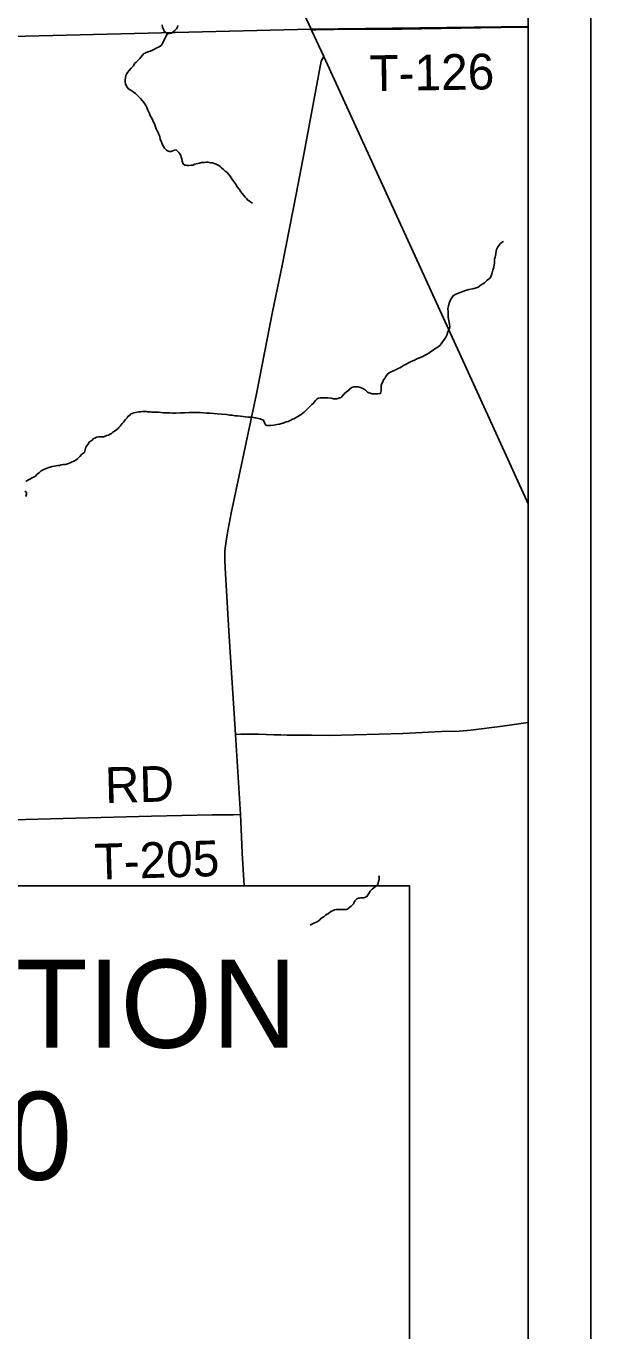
# Model space of a CAD drawing. Extents: x 0 to 34, y 0 to 22.
# Drawn here: x 8.364 to 9.262, y 17.696 to 19.769 of the extents above; entities that cross this region are included whole.
import ezdxf

# ---------------------------------------------------------------- set-up
doc = ezdxf.new("R2010")
doc.units = 0
for name, color, linetype in [('GM_X_County', 7, 'Continuous'), ('GM_X_County_Road', 7, 'Continuous'), ('GM_X_Minor_Lake', 7, 'Continuous'), ('GM_X_Minor_River', 7, 'Continuous'), ('GM_X_State_Route', 7, 'Continuous'), ('GM_X_Township', 7, 'Continuous'), ('GM_X_Township_Road', 7, 'Continuous'), ('GM_X_Township_Road_Text', 7, 'Continuous'), ('SH_Border', 7, 'Continuous'), ('SH_Data', 7, 'Continuous'), ('SH_Text', 7, 'Continuous')]:
    doc.layers.add(name, color=color, linetype=linetype)

msp = doc.modelspace()

# ---------------------------------------------------------------- linework, layer by layer
at = {"layer": 'GM_X_County'}
msp.add_lwpolyline([(9.1622, 14.342), (9.1622, 21.1385), (2.3622, 21.1385), (2.3622, 14.3385), (9.0003, 14.3385)], dxfattribs=at)
at = {"layer": 'GM_X_County_Road'}
msp.add_lwpolyline([(8.7102, 18.4031), (8.7074, 18.4551), (8.7054, 18.4937), (8.7044, 18.5161), (8.6966, 18.6436), (8.6868, 18.7992), (8.6805, 18.8991), (8.6795, 18.9191), (8.6795, 18.9355), (8.6817, 18.9511), (8.6849, 18.9697), (8.69, 18.9951), (8.7298, 19.1848), (8.7557, 19.3152), (8.7706, 19.389), (8.7936, 19.505), (8.8058, 19.5687), (8.8326, 19.7135), (8.8373, 19.7211)], dxfattribs=at)
at = {"layer": 'GM_X_Minor_Lake'}
msp.add_lwpolyline([(8.5798, 19.7717), (8.5806, 19.7679), (8.5818, 19.7656), (8.5833, 19.7614), (8.5864, 19.7588), (8.5883, 19.7577), (8.5902, 19.7577), (8.5925, 19.7577), (8.5947, 19.7581), (8.5977, 19.7604), (8.6004, 19.7627), (8.603, 19.7654), (8.6045, 19.7677), (8.6049, 19.7707)], dxfattribs=at)
at = {"layer": 'GM_X_Minor_River'}
for points in [[(8.5883, 19.7577), (8.5789, 19.739), (8.5755, 19.7367), (8.5714, 19.7347), (8.568, 19.7328), (8.5646, 19.7313), (8.5608, 19.7297), (8.5578, 19.7286), (8.5547, 19.7274), (8.5528, 19.7266), (8.551, 19.7259), (8.5491, 19.7239), (8.5461, 19.7201), (8.5446, 19.7182), (8.5415, 19.7148), (8.5389, 19.7121), (8.5363, 19.7098), (8.5344, 19.7064), (8.5306, 19.7025), (8.5276, 19.6987), (8.525, 19.6957), (8.5235, 19.693), (8.5224, 19.6907), (8.5213, 19.6835), (8.5213, 19.6804), (8.5217, 19.6778), (8.5229, 19.6751), (8.5244, 19.6725), (8.5259, 19.6702), (8.5282, 19.6687), (8.5301, 19.6676), (8.5324, 19.6661), (8.5355, 19.6638), (8.5374, 19.6623), (8.5397, 19.6604), (8.5424, 19.6574), (8.5454, 19.6544), (8.5481, 19.651), (8.5508, 19.6483), (8.5527, 19.6457), (8.5542, 19.6431), (8.5554, 19.64), (8.5569, 19.637), (8.5585, 19.6336), (8.56, 19.6306), (8.5612, 19.6275), (8.5627, 19.6245), (8.5647, 19.6211), (8.5658, 19.6181), (8.5674, 19.615), (8.5685, 19.6124), (8.5693, 19.6093), (8.5705, 19.6063), (8.572, 19.6029), (8.5735, 19.6003), (8.5747, 19.5972), (8.5762, 19.5938), (8.577, 19.59), (8.5782, 19.5862), (8.5794, 19.584), (8.5805, 19.5809), (8.5821, 19.5779), (8.584, 19.5753), (8.5867, 19.5722), (8.5886, 19.5711), (8.5916, 19.57), (8.5943, 19.57), (8.5999, 19.5723), (8.6022, 19.5727), (8.6049, 19.5701), (8.6072, 19.5678), (8.6087, 19.5656), (8.6099, 19.5637), (8.6103, 19.561), (8.6111, 19.5584), (8.6118, 19.5549), (8.6126, 19.5531), (8.6134, 19.5508), (8.6161, 19.5485), (8.618, 19.5482), (8.6202, 19.5478), (8.6229, 19.5478), (8.6259, 19.5482), (8.6286, 19.5486), (8.632, 19.5498), (8.6343, 19.5506), (8.6365, 19.5509), (8.6392, 19.5517), (8.6426, 19.5525), (8.6468, 19.5529), (8.6506, 19.553), (8.6532, 19.553), (8.6551, 19.5526), (8.6574, 19.5522), (8.6601, 19.5519), (8.6627, 19.5511)], [(8.6627, 19.5511), (8.6658, 19.55), (8.6681, 19.5489), (8.6703, 19.5478), (8.6726, 19.5459), (8.6745, 19.544), (8.6776, 19.5418), (8.6803, 19.5391), (8.6826, 19.5372), (8.686, 19.5335), (8.6879, 19.5308), (8.691, 19.5267), (8.6937, 19.5229), (8.6964, 19.5187), (8.6994, 19.5142), (8.7025, 19.5104), (8.7052, 19.5062), (8.7121, 19.4975), (8.714, 19.4957), (8.7163, 19.493), (8.7182, 19.4919), (8.7209, 19.4896), (8.7228, 19.4885), (8.7239, 19.4878)], [(8.9111, 19.1859), (8.9133, 19.1852), (8.9228, 19.1849), (8.9255, 19.1853), (8.9274, 19.1857), (8.9285, 19.1898), (8.9285, 19.194), (8.9284, 19.1963), (8.9284, 19.1982), (8.9295, 19.2016), (8.9307, 19.2043), (8.9322, 19.207), (8.9344, 19.2104), (8.9359, 19.2127), (8.9378, 19.2157), (8.9412, 19.2184), (8.9453, 19.2207), (8.9491, 19.2223), (8.9514, 19.2231), (8.9533, 19.2242), (8.9555, 19.2254), (8.9578, 19.2265), (8.9605, 19.2281), (8.9639, 19.23), (8.968, 19.2323), (8.9718, 19.2342), (8.976, 19.2362), (8.9801, 19.2381), (8.9847, 19.2404), (8.9892, 19.2423), (8.9937, 19.2439), (8.9971, 19.2458), (9.0005, 19.2477), (9.0039, 19.2497), (9.0066, 19.2516), (9.0096, 19.2531), (9.0153, 19.2574), (9.0183, 19.2589), (9.0221, 19.2623), (9.0236, 19.2643), (9.0284, 19.2715), (9.0307, 19.2742), (9.0329, 19.2784), (9.0344, 19.2833), (9.0363, 19.2879), (9.0374, 19.2917), (9.037, 19.2955), (9.0362, 19.2985), (9.0358, 19.3016), (9.0354, 19.3039), (9.035, 19.3069), (9.035, 19.3111), (9.0346, 19.316), (9.0345, 19.3202), (9.0349, 19.3225), (9.0352, 19.3248), (9.0356, 19.3267), (9.0364, 19.3293), (9.0378, 19.3335), (9.0393, 19.3362), (9.0427, 19.3408), (9.0461, 19.3431), (9.0484, 19.3438), (9.0514, 19.345), (9.0552, 19.3466), (9.0609, 19.3489), (9.0677, 19.3508), (9.0737, 19.352), (9.076, 19.3524), (9.0825, 19.3547), (9.0874, 19.3582), (9.0927, 19.3616), (9.0968, 19.3655), (9.1006, 19.3682), (9.1024, 19.3712), (9.1039, 19.3739), (9.1047, 19.3773), (9.1058, 19.3815), (9.1073, 19.3861), (9.108, 19.3899), (9.1084, 19.3929), (9.1087, 19.3963), (9.1087, 19.3998), (9.1094, 19.402), (9.1098, 19.4043), (9.1105, 19.4078), (9.1109, 19.4116), (9.1116, 19.4146), (9.1131, 19.4177), (9.1154, 19.4207), (9.118, 19.4241), (9.121, 19.4264), (9.1225, 19.4272)], [(8.5686, 19.1557), (8.5716, 19.1557), (8.575, 19.1557), (8.5785, 19.1554), (8.5815, 19.155), (8.5841, 19.155), (8.5868, 19.1547), (8.5895, 19.1547), (8.5925, 19.1547), (8.5967, 19.1544), (8.6016, 19.1544), (8.6092, 19.1548), (8.6156, 19.1549), (8.6229, 19.1553), (8.6293, 19.1554), (8.635, 19.1554), (8.6403, 19.1551), (8.6456, 19.1547), (8.6506, 19.1544), (8.6559, 19.154), (8.662, 19.1537), (8.668, 19.153), (8.6745, 19.1526), (8.6825, 19.1519), (8.6874, 19.1512), (8.6916, 19.1509), (8.6954, 19.1501), (8.6999, 19.1498), (8.7045, 19.1494), (8.7087, 19.1491), (8.7125, 19.1484), (8.7163, 19.148), (8.7193, 19.1477), (8.722, 19.1477), (8.725, 19.1473), (8.7273, 19.147), (8.7292, 19.1466), (8.733, 19.1459), (8.736, 19.1451), (8.7379, 19.1444), (8.7398, 19.1436), (8.7414, 19.1433), (8.7418, 19.1414), (8.7433, 19.1379), (8.7445, 19.1357), (8.7467, 19.1346), (8.749, 19.1346), (8.7528, 19.1346), (8.7577, 19.1354), (8.7623, 19.1362), (8.7668, 19.137), (8.7699, 19.1378), (8.7725, 19.1385), (8.7748, 19.1393), (8.7774, 19.1405), (8.7805, 19.1409), (8.7824, 19.142), (8.7846, 19.1432), (8.7873, 19.1447), (8.7892, 19.1455), (8.7914, 19.1463), (8.7948, 19.1482), (8.7967, 19.1494), (8.799, 19.1509), (8.8009, 19.152), (8.8039, 19.154), (8.8058, 19.1559), (8.8084, 19.1586), (8.8111, 19.1609), (8.8133, 19.1635), (8.816, 19.1658), (8.8182, 19.1678), (8.8201, 19.1697), (8.8239, 19.1746), (8.8265, 19.1769), (8.8288, 19.1781), (8.831, 19.1785), (8.8345, 19.1785), (8.8375, 19.1785), (8.8436, 19.1786), (8.8485, 19.1779), (8.8527, 19.1771), (8.8557, 19.1768), (8.8576, 19.1768), (8.8625, 19.1787), (8.8644, 19.1791), (8.8693, 19.1848), (8.8735, 19.1887), (8.8761, 19.1902), (8.878, 19.1925), (8.8814, 19.1952), (8.884, 19.196), (8.8875, 19.196), (8.8916, 19.196), (8.8954, 19.1953), (8.8981, 19.1942), (8.9004, 19.1931), (8.9031, 19.1908), (8.9065, 19.1878), (8.9084, 19.1867), (8.9111, 19.1859)], [(8.3633, 19.0455), (8.3667, 19.0478), (8.3766, 19.0528), (8.3788, 19.0543), (8.3803, 19.0563), (8.3834, 19.0589), (8.3852, 19.0601), (8.3879, 19.0624), (8.3932, 19.0651), (8.397, 19.0666), (8.4, 19.0678), (8.4019, 19.0682), (8.4053, 19.0694), (8.4087, 19.0701), (8.4117, 19.0705), (8.4144, 19.0709), (8.417, 19.0713), (8.4197, 19.0721), (8.4227, 19.0729), (8.4261, 19.0729), (8.428, 19.0733), (8.4311, 19.0741), (8.4337, 19.0753), (8.4371, 19.0768), (8.4398, 19.078), (8.4428, 19.0795), (8.4454, 19.0818), (8.4492, 19.0856), (8.453, 19.0895), (8.4564, 19.0918), (8.4571, 19.0937), (8.4589, 19.1002), (8.4619, 19.1044), (8.4642, 19.1082), (8.4687, 19.1116), (8.471, 19.1139), (8.4729, 19.1147), (8.4755, 19.1159), (8.4789, 19.1166), (8.4812, 19.1167), (8.4839, 19.1167), (8.4869, 19.1167), (8.4899, 19.1175), (8.4918, 19.1186), (8.4945, 19.1194), (8.4975, 19.121), (8.4994, 19.1221), (8.5013, 19.1236), (8.5032, 19.1252), (8.5054, 19.1263), (8.5084, 19.1286), (8.51, 19.1298), (8.5111, 19.1313), (8.5133, 19.1336), (8.5148, 19.1355), (8.5167, 19.1378), (8.5186, 19.1397), (8.5201, 19.142), (8.522, 19.1443), (8.5246, 19.147), (8.5257, 19.1489), (8.528, 19.1508), (8.5303, 19.1531), (8.5322, 19.1539), (8.5348, 19.1547), (8.5405, 19.1558), (8.5428, 19.1562), (8.5454, 19.1566), (8.5477, 19.1567), (8.55, 19.1567), (8.5526, 19.1567), (8.5549, 19.1567), (8.5568, 19.1563), (8.5606, 19.1564), (8.5629, 19.156), (8.5652, 19.156), (8.5686, 19.1557)], [(8.3631, 19.0219), (8.3646, 19.0257), (8.3642, 19.0284), (8.3619, 19.0303)], [(8.8151, 18.3406), (8.818, 18.342), (8.8214, 18.3436), (8.8241, 18.3448), (8.8263, 18.3459), (8.8286, 18.3474), (8.8309, 18.349), (8.8331, 18.3517), (8.8369, 18.3536), (8.8399, 18.3563), (8.8426, 18.3578), (8.8445, 18.359), (8.8482, 18.362), (8.8509, 18.3632), (8.8543, 18.3647), (8.8573, 18.3655), (8.8611, 18.3655), (8.8649, 18.3652), (8.8683, 18.3652), (8.8702, 18.3652), (8.8729, 18.3656), (8.8748, 18.366), (8.8785, 18.3691), (8.8808, 18.3706), (8.8842, 18.3745), (8.8853, 18.3767), (8.8864, 18.379), (8.8894, 18.3821), (8.8921, 18.3832), (8.894, 18.3836), (8.8963, 18.384), (8.8989, 18.3841), (8.9008, 18.3841), (8.9035, 18.3849), (8.9057, 18.386), (8.9084, 18.3906), (8.911, 18.3944), (8.914, 18.3978), (8.917, 18.4002), (8.9193, 18.4017), (8.9212, 18.4036), (8.9231, 18.4051), (8.9242, 18.4097), (8.9249, 18.4131), (8.9249, 18.415), (8.9252, 18.4173), (8.9248, 18.4188)]]:
    msp.add_lwpolyline(points, dxfattribs=at)
at = {"layer": 'GM_X_State_Route'}
msp.add_lwpolyline([(9.1622, 19.01), (9.0834, 19.1826), (8.9908, 19.3851), (8.8961, 19.5922), (8.8373, 19.7211), (8.8176, 19.7629), (8.8169, 19.7645), (8.7845, 19.8343)], dxfattribs=at)
at = {"layer": 'GM_X_Township'}
for p, q in [((9.1622, 19.7691), (9.1622, 19.7699)), ((9.1622, 14.342), (9.1622, 19.7691))]:
    msp.add_line(p, q, dxfattribs=at)
for points in [[(4.3953, 21.1385), (4.3964, 21.0758), (4.3978, 20.7562), (4.4083, 20.0336), (4.4103, 19.8926), (4.4134, 19.6764), (5.8028, 19.7101), (6.782, 19.7315), (7.8005, 19.7395), (8.817, 19.7645), (9.1622, 19.7691)], [(9.1622, 19.7691), (8.817, 19.7645), (7.8005, 19.7395), (6.782, 19.7315), (5.8028, 19.7101), (4.4134, 19.6764), (4.4176, 19.4076), (4.4274, 18.8628), (4.4298, 18.3764)]]:
    msp.add_lwpolyline(points, dxfattribs=at)
at = {"layer": 'GM_X_Township_Road'}
for points in [[(8.8176, 19.7629), (8.8319, 19.7639), (8.8529, 19.7642), (8.9606, 19.7646), (9.1185, 19.767), (9.1622, 19.7677)], [(9.1622, 18.6625), (9.1211, 18.6569), (9.071, 18.6505), (9.0528, 18.6488), (9.024, 18.6485), (8.9935, 18.6469), (8.9627, 18.6452), (8.9252, 18.6438), (8.8852, 18.6429), (8.8454, 18.6421), (8.8173, 18.6422), (8.7994, 18.6424), (8.7884, 18.6424), (8.7787, 18.6426), (8.7689, 18.6431), (8.7577, 18.6431), (8.7452, 18.6436), (8.7332, 18.6439), (8.7154, 18.6443), (8.7052, 18.6441), (8.6966, 18.6436)], [(8.7044, 18.5161), (8.6927, 18.5158), (8.6595, 18.5159), (8.563, 18.5139), (8.3224, 18.5075), (8.2597, 18.5069), (8.0394, 18.5019), (7.9373, 18.4983), (7.8805, 18.4957), (7.8416, 18.4941), (7.8125, 18.4935)]]:
    msp.add_lwpolyline(points, dxfattribs=at)
at = {"layer": 'SH_Border'}
msp.add_lwpolyline([(6.9977, 18.4031), (8.9734, 18.4031), (8.9734, 17.6552), (6.9977, 17.6552)], close=True, dxfattribs=at)
at = {"layer": 'SH_Data'}
msp.add_line((9.2617, 21.2383), (9.2617, 14.2383), dxfattribs=at)

# ---------------------------------------------------------------- texts
at = {"layer": 'GM_X_Township_Road_Text'}
for s, rotation, p in [('T-126', 0.8421, (8.91, 19.6661)), ('RD', 1.4826, (8.4897, 18.5345)), ('T-205', 1.6848, (8.4732, 18.4128))]:
    msp.add_text(s, height=0.05682, rotation=rotation, dxfattribs=at).set_placement(p)
at = {"layer": 'SH_Text'}
for s, p in [('END ACQUISITION', (7.1303, 18.1456)), ('STA 640+21.90', (7.1303, 17.9356))]:
    msp.add_text(s, height=0.14, dxfattribs=at).set_placement(p)

doc.saveas('drawing.dxf')
